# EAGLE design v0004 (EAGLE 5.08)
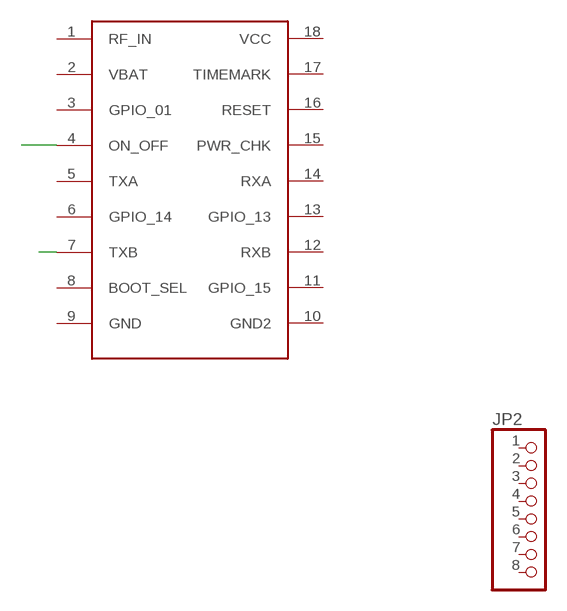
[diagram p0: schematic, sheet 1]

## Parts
JP2  PINHD-1X8  [1X08]
U$1  ISM300  [ISM300F2]

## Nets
N$8: U$1.7(TXB)
N$9: U$1.4(ON_OFF)
Unconnected: JP2.1 JP2.2 JP2.3 JP2.4 JP2.5 JP2.6 JP2.7 JP2.8 U$1.1(RF_IN) U$1.2(VBAT) U$1.3(GPIO_01) U$1.5(TXA) U$1.6(GPIO_14) U$1.8(BOOT_SEL) U$1.9(GND) U$1.10(GND2) U$1.11(GPIO_15) U$1.12(RXB) U$1.13(GPIO_13) U$1.14(RXA) U$1.15(PWR_CHK) U$1.16(RESET) U$1.17(TIMEMARK) U$1.18(VCC)

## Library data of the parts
JP2 = pinhead:PINHD-1X8: PIN HEADER
U$1 = inventek:ISM300

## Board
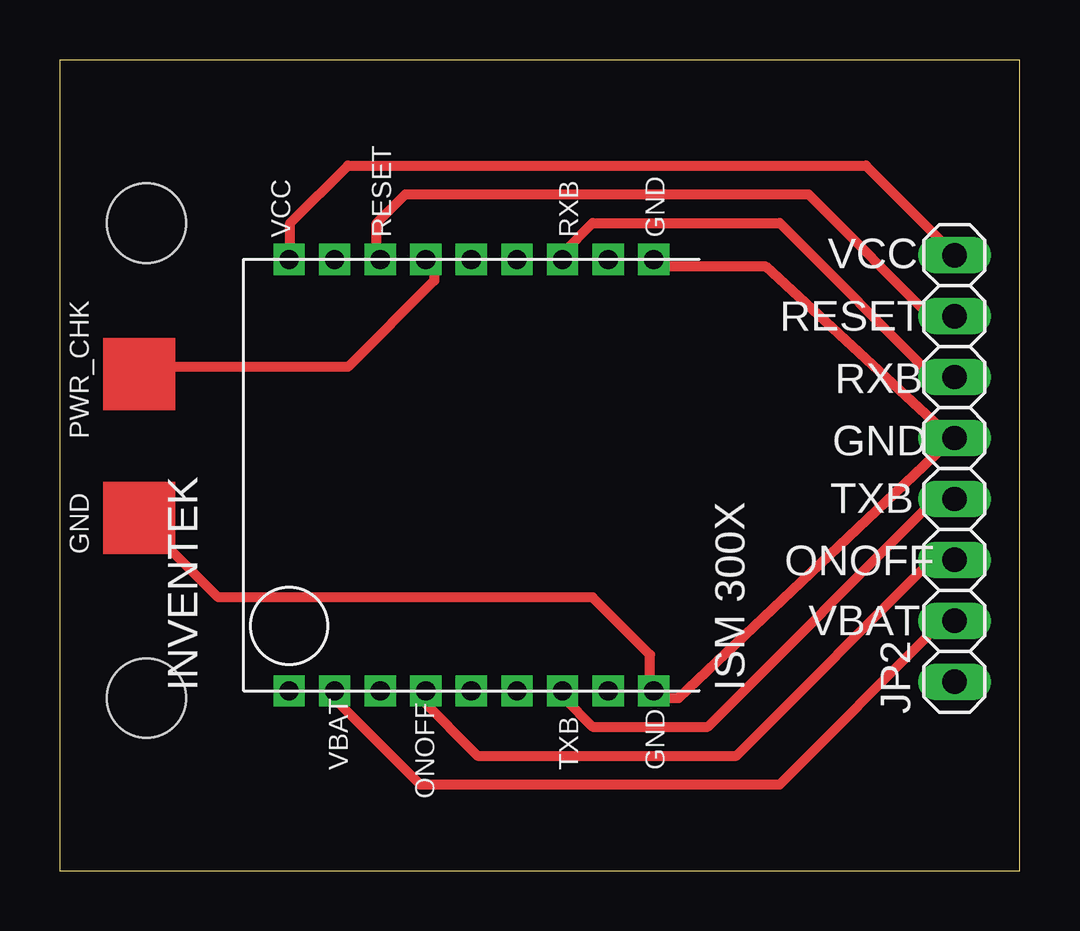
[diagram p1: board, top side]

Size 40 x 33.8 mm. Coordinates in mm from the lower left corner, seen from the top.
Outline: 0,0 40,0 40,33.8 0,33.8 0,0
Copper layers (1*16): Top 0.035mm / dielectric 1.5mm / Bottom 0.035mm
Design rules "default": minimum track width 10mil, minimum drill 24mil, track to track 8mil, track to pad 8mil, pad to pad 8mil, via to via 8mil, smd to smd 8mil, copper to edge 40mil, drill to drill 8mil, minimum pad ring 10mil, minimum via ring 8mil, stop-mask expansion 4mil, vias tented up to drill 0mil, thermal gap 10mil

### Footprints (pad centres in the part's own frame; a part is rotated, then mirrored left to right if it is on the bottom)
1X08 = drill 1.016 long: 1 -8.89,0; 2 -6.35,0; 3 -3.81,0; 4 -1.27,0; 5 1.27,0; 6 3.81,0; 7 6.35,0; 8 8.89,0
ISM300F2 = drill 0.8 square: 1 -15.2,9.5; 2 -15.2,7.6; 3 -15.2,5.7; 4 -15.2,3.8; 5 -15.2,1.9; 6 -15.2,0; 7 -15.2,-1.9; 8 -15.2,-3.8; 9 -15.2,-5.7; 10 2.78,-5.7; 11 2.78,-3.8; 12 2.78,-1.9; 13 2.78,0; 14 2.78,1.9; 15 2.78,3.8; 16 2.78,5.7; 17 2.78,7.6; 18 2.78,9.5
STAND-OFF = hole 3.302: 0,0

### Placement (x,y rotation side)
JP2  37.29,16.77 90 top
U$1  19.05,22.7 90 top
U$2  [STAND-OFF]  3.6,27 0 top
U$3  [STAND-OFF]  3.6,7.2 0 top

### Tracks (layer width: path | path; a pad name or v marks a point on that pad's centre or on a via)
N$1
  Top 0.406: 9.6,25.8 9.6,27 12,29.4 33.6,29.4 37.2,25.8
N$2
  Top 0.406: 21,25.8 22.2,27 30,27 36.6,20.4
N$4
  Top 0.406: 24.6,25.2 29.4,25.2 37.2,18 25.8,7.2 24.6,7.2
N$5
  Top 0.406: 21,7.2 22.2,6 27,6 36.6,15.6
N$6
  Top 0.406: 15,7.2 17.4,4.8 28.2,4.8 36.6,13.2
N$7
  Top 0.406: 11.4,7.2 15,3.6 30,3.6 36.6,10.2
N$10
  Top 0.406: 13.2,25.8 13.2,27 14.4,28.2 31.2,28.2 36.6,22.8
N$11
  Top 0.406: 15.6,25.2 15.6,24.6 12,21 4.2,21
N$12
  Top 0.406: 24.6,7.8 24.6,9 22.2,11.4 6.6,11.4 3.6,14.4
(copper drawn outside any net)
  shapes: Top area x2

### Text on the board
tPlace: VCC | RESET | RXB | GND | VCC | RESET | RXB | PWR_CHK | GND | TXB | GND | ONOFF | VBAT | VBAT | TXB | GND | ONOFF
